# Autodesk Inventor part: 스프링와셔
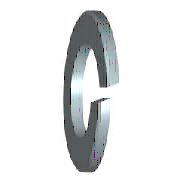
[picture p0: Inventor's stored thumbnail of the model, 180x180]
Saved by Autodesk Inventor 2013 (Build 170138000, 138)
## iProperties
Created: 2012-02
Part Number: 스프링와셔
Material: 강철, 연강
Description: 스프링 와셔
Document SubType Name: Modeling
Standard: JIS B 1251
Designer: mduedu
Standards Organization: JIS
Language: ko-KR
Size Designation: 번호 2 4
Categories: <MemberInstance><Categories><Category DisplayName="조임쇠" InternalName="e4da775c-781d-43d5-af7c-5136215cf5a6" Mnemonic="FSTN"><Category DisplayName="와셔" InternalN
Density: 7.86 g/cm^3
Mass: 0.24727 g
Surface Area: 1.02615 cm^2
Volume: 0.0314593 cm^3
IsCustomPart: 1
Author: mduedu
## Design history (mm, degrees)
sketch "스케치1"
  geometry: C1 r 3.8 at (0, 0); C2 r 2.05 at (0, 0); 1 further point
  constraints: 2 centre point, 2 coincident
  dimensions: "d0" = 4.1 diameter of C2 (= SD1); "d1" = 7.6 diameter of C1 (= SD2)
extrude "본체" new body sketch "스케치1" distance "d2" = 1 (= SD); taper "d3" = 0 deg
sketch "스케치2"
  geometry: L1 (0, -2.05)-(0, 2.05) reference; L2 (1, 3.8)-(1, -3.8) reference; L3 (-1.2, 0)-(7.2, 0) reference; L4 (0, -0.2)-(1, 0.164); L5 (0, 0.2)-(1, 0.564)
  constraints: 4 end point, 4 point on line, 1 parallel
  dimensions: "d4" = 0.2 distance from line of L3 L4.start (= 0.2 x SD); "d5" = 0.2 distance from line of L3 L5.start (= 0.2 x SD); "d6" = 70 deg angle of L2 L4 (= FAWI)
extrude "절단부" cut sketch "스케치2" stored distance "d7" = 1 (= SD); taper "d8" = 0 deg
workaxis "Work Axis1"
workplane "Work Plane1"
body "Solid1"
other parameters: "SD1" = 4.1 [user parameter; used in 1 equation term], "SD2" = 7.6 [user parameter; used in 1 equation term], "SD" = 1 [user parameter; used in 4 equation terms], "FAWI" = 70 deg [user parameter; used in 1 equation term], "d9" = 0, "d10" = 0, "d11" = 0, "d12" = 0, "SDI" = 1.4 [user parameter], "NND" = 4 [user parameter]
